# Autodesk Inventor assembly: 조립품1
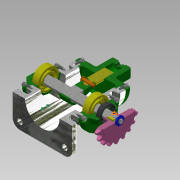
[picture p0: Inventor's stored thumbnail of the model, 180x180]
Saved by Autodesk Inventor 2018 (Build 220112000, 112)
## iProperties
Created: 2021-03
Part Number: 조립품1
Material: 일반
Document SubType Name: Assembly
Designer: home
Author: home
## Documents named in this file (18)
- C:\Users\home\Desktop\710306V1025\조립품1.iam
- C:\Users\home\Desktop\710306V1025\본체.ipt
- C:\Users\home\Desktop\710306V1025\베어링 17 x 40 x 12.ipt
- C:\Users\home\Desktop\710306V1025\뒤커버.ipt
- C:\Users\home\Desktop\710306V1025\편심축.ipt
- C:\Users\home\Desktop\710306V1025\앞커버.ipt
- C:\Users\home\Desktop\710306V1025\오일 실 17 30 8.ipt
- C:\Users\home\Desktop\710306V1025\스프로킷.ipt
- C:\Users\home\Desktop\710306V1025\키 4 x 4 x 12.ipt
- C:\Users\home\Desktop\710306V1025\와셔 4x16.ipt
- C:\Users\home\Desktop\710306V1025\볼트 M4 x 8.ipt
- C:\Users\home\Desktop\710306V1025\멈춤나사 M3.ipt
- C:\Users\home\Desktop\710306V1025\링크.ipt
- C:\Users\home\Desktop\710306V1025\슬라이더.ipt
- C:\Users\home\Desktop\710306V1025\클레비스 핀 6 x 22.ipt
- 클레비스 핀 6 x 22.ipt
- C:\Users\home\Desktop\710306V1025\덮개.ipt
- C:\Users\home\Desktop\710306V1025\볼트 M4 x 10.ipt
